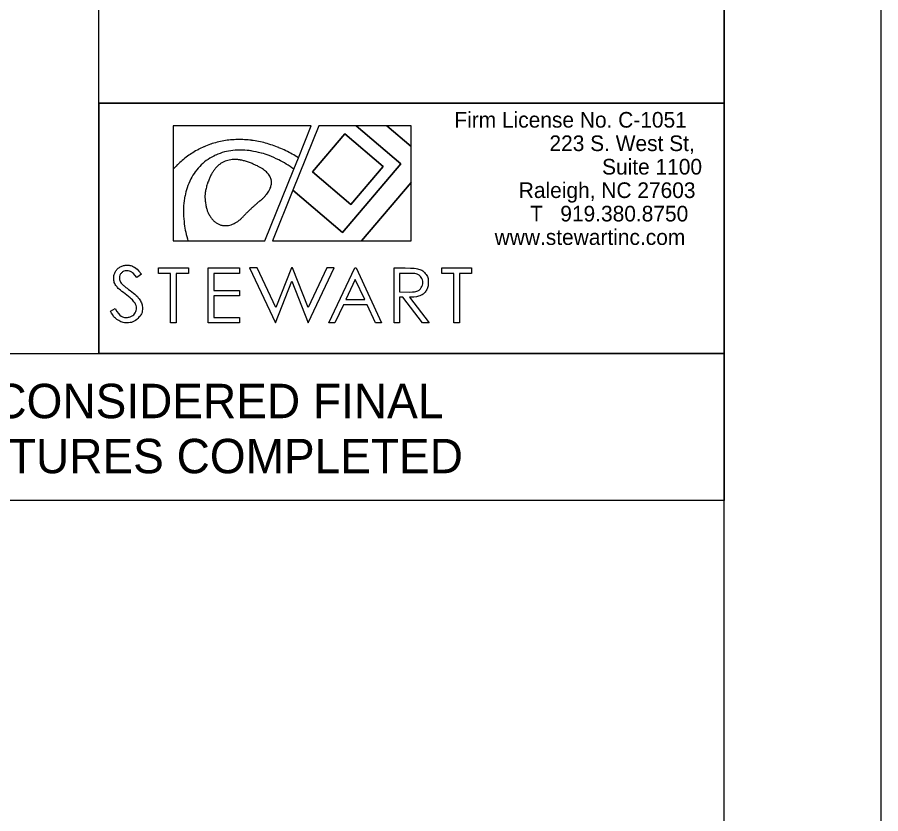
# Model space of a CAD drawing. Extents: x 885343.6 to 885383.5, y 651350.8 to 651372.8.
# Drawn here: x 885374.838 to 885377.598, y 651367.24 to 651369.786 of the extents above; entities that cross this region are included whole.
import ezdxf

# ---------------------------------------------------------------- set-up
doc = ezdxf.new("R2010")
doc.units = 0
for name, color, linetype in [('Default', 7, 'Continuous'), ('Sheet Plan And Profile CELL', 7, 'Continuous'), ('Sheet Plan CELL', 7, 'Continuous'), ('Sheet Sticker Exception Certification CELL', 7, 'Continuous'), ('Stewart Plot Border Xerox6279 and LJ5000', 7, 'Continuous')]:
    doc.layers.add(name, color=color, linetype=linetype)

msp = doc.modelspace()

# ---------------------------------------------------------------- linework, layer by layer
at = {"layer": 'Default'}
for p, q in [((885375.7773, 651369.4388), (885375.3358, 651369.4388)), ((885375.3358, 651369.4388), (885375.3358, 651369.2998)), ((885375.8019, 651369.4388), (885375.7189, 651369.2326)), ((885375.7362, 651369.3367), (885375.7773, 651369.4388)), ((885375.9209, 651369.4388), (885375.8019, 651369.4388)), ((885375.9209, 651369.4388), (885376.0639, 651369.317)), ((885376.0188, 651369.4388), (885375.9209, 651369.4388)), ((885376.0639, 651369.317), (885375.9209, 651369.4388)), ((885376.0965, 651369.4388), (885376.0188, 651369.4388)), ((885376.0188, 651369.4388), (885376.0965, 651369.3727)), ((885376.0965, 651369.3727), (885376.0188, 651369.4388)), ((885376.0965, 651369.3727), (885376.0965, 651369.4388)), ((885375.5862, 651369.3923), (885375.5864, 651369.3923)), ((885375.4347, 651369.372), (885375.4342, 651369.3714)), ((885375.456, 651369.3801), (885375.4551, 651369.3798)), ((885376.0965, 651369.2574), (885376.0965, 651369.3727)), ((885375.5845, 651369.3582), (885375.5853, 651369.3586)), ((885375.6959, 651369.3591), (885375.696, 651369.359)), ((885375.7216, 651369.3005), (885375.7362, 651369.3367)), ((885376.0639, 651369.317), (885375.8772, 651369.0978)), ((885375.8772, 651369.0978), (885376.0639, 651369.317)), ((885375.9036, 651369.187), (885376.0073, 651369.3087)), ((885375.3358, 651369.2998), (885375.3358, 651369.0708)), ((885375.6293, 651369.0708), (885375.7216, 651369.3005)), ((885376.0965, 651369.2574), (885375.9376, 651369.0708)), ((885375.9376, 651369.0708), (885376.0965, 651369.2574)), ((885376.0965, 651369.0708), (885376.0965, 651369.2574)), ((885375.7189, 651369.2326), (885375.6539, 651369.0708)), ((885375.8772, 651369.0978), (885375.7189, 651369.2326)), ((885375.7189, 651369.2326), (885375.8772, 651369.0978)), ((885375.3358, 651369.0708), (885375.3833, 651369.0708)), ((885375.3833, 651369.0708), (885375.6293, 651369.0708)), ((885375.6539, 651369.0708), (885375.9376, 651369.0708)), ((885375.9376, 651369.0708), (885376.0965, 651369.0708)), ((885375.6041, 651368.9842), (885375.5802, 651368.9842)), ((885375.5802, 651368.9842), (885375.6626, 651368.8092)), ((885375.6636, 651368.8581), (885375.6041, 651368.9842)), ((885375.7141, 651368.9842), (885375.6636, 651368.8581)), ((885375.7175, 651368.9842), (885375.7141, 651368.9842)), ((885375.767, 651368.8581), (885375.7175, 651368.9842)), ((885375.8266, 651368.9842), (885375.767, 651368.8581)), ((885375.7678, 651368.8092), (885375.8504, 651368.9842)), ((885375.8504, 651368.9842), (885375.8266, 651368.9842)), ((885375.6626, 651368.8092), (885375.7157, 651368.9417)), ((885375.7157, 651368.9417), (885375.7678, 651368.8092))]:
    msp.add_line(p, q, dxfattribs=at)
msp.add_lwpolyline([(885377.0978, 651369.5109), (885375.0978, 651369.5109), (885375.0978, 651368.7109), (885377.0978, 651368.7109)], close=True, dxfattribs=at)
for points in [[(885375.7814, 651369.2911), (885375.885, 651369.4128), (885376.0073, 651369.3087), (885375.9036, 651369.187), (885375.7814, 651369.2911)], [(885376.0073, 651369.3087), (885375.885, 651369.4128), (885375.7814, 651369.2911), (885375.9036, 651369.187)], [(885375.4155, 651369.3626), (885375.417, 651369.3635)], [(885375.6179, 651369.3515), (885375.617, 651369.3511)], [(885375.3499, 651369.3143), (885375.3487, 651369.3135)], [(885375.6129, 651369.1982), (885375.6112, 651369.1969)], [(885375.6155, 651369.1998), (885375.6141, 651369.199)], [(885375.6092, 651369.1953), (885375.6068, 651369.1933)], [(885375.5652, 651369.1544), (885375.5632, 651369.1524)], [(885375.2889, 651368.9671), (885375.2889, 651368.9842), (885375.3847, 651368.9842), (885375.3847, 651368.9671), (885375.3457, 651368.9671), (885375.3457, 651368.8092), (885375.3279, 651368.8092), (885375.3279, 651368.9671), (885375.2889, 651368.9671)], [(885375.448, 651368.9842), (885375.5484, 651368.9842), (885375.5484, 651368.9671), (885375.4655, 651368.9671), (885375.4655, 651368.9122), (885375.5477, 651368.9122), (885375.5477, 651368.8951), (885375.4655, 651368.8951), (885375.4655, 651368.8263), (885375.5477, 651368.8263), (885375.5477, 651368.8092), (885375.448, 651368.8092), (885375.448, 651368.9842)], [(885375.9205, 651368.9842), (885376.0021, 651368.8092), (885375.9832, 651368.8092), (885375.9557, 651368.8669), (885375.8803, 651368.8669), (885375.8531, 651368.8092), (885375.8336, 651368.8092), (885375.9162, 651368.9842), (885375.9205, 651368.9842)], [(885376.0424, 651368.9842), (885376.0772, 651368.9842)], [(885376.0913, 651368.8904), (885376.1542, 651368.8092), (885376.1325, 651368.8092), (885376.0696, 651368.8904), (885376.0598, 651368.8904), (885376.0598, 651368.8092), (885376.0424, 651368.8092), (885376.0424, 651368.9842)], [(885376.1943, 651368.9671), (885376.1943, 651368.9842), (885376.2901, 651368.9842), (885376.2901, 651368.9671), (885376.2511, 651368.9671), (885376.2511, 651368.8092), (885376.2333, 651368.8092), (885376.2333, 651368.9671), (885376.1943, 651368.9671)], [(885375.2344, 651368.9643), (885375.2202, 651368.9535)], [(885376.0598, 651368.9671), (885376.0598, 651368.9075), (885376.0899, 651368.9073)], [(885376.0906, 651368.9671), (885376.0598, 651368.9671)], [(885375.9182, 651368.9471), (885375.8883, 651368.8837), (885375.9481, 651368.8837), (885375.9182, 651368.9471)], [(885375.1351, 651368.8462), (885375.15, 651368.8551)]]:
    msp.add_lwpolyline(points, dxfattribs=at)
for centre, radius, start, end in [((885375.5456, 651369.1125), 0.2822, 99.7438, 104.178), ((885375.5456, 651369.1125), 0.2822, 99.7438, 104.178), ((885375.5462, 651369.1088), 0.286, 95.339, 99.7438), ((885375.5462, 651369.1088), 0.286, 95.339, 99.7438), ((885375.5467, 651369.1035), 0.2913, 91.0141, 95.339), ((885375.5467, 651369.1035), 0.2913, 91.0141, 95.339), ((885375.547, 651369.0858), 0.309, 86.8145, 91.0141), ((885375.547, 651369.0858), 0.309, 86.8145, 91.0141), ((885375.547, 651369.0858), 0.309, 82.6822, 86.8145), ((885375.547, 651369.0858), 0.309, 82.6822, 86.8145), ((885375.5431, 651369.0564), 0.3386, 78.75, 82.6822), ((885375.5431, 651369.0564), 0.3386, 78.75, 82.6822), ((885375.5495, 651369.1106), 0.2855, 117.649, 121.981), ((885375.5495, 651369.1106), 0.2855, 117.649, 121.981), ((885375.5372, 651369.1304), 0.2622, 113.1331, 117.649), ((885375.5372, 651369.1304), 0.2622, 113.1331, 117.649), ((885375.5456, 651369.1125), 0.2822, 108.6948, 113.1331), ((885375.5456, 651369.1125), 0.2822, 108.6948, 113.1331), ((885375.5427, 651369.1238), 0.2705, 104.178, 108.6948), ((885375.5427, 651369.1238), 0.2705, 104.178, 108.6948), ((885375.5454, 651369.0679), 0.3269, 74.8634, 78.75), ((885375.5454, 651369.0679), 0.3269, 74.8634, 78.75), ((885375.5332, 651369.0228), 0.3736, 71.2279, 74.8634), ((885375.5332, 651369.0228), 0.3736, 71.2279, 74.8634), ((885375.5406, 651369.0448), 0.3505, 67.6108, 71.2279), ((885375.5406, 651369.0448), 0.3505, 67.6108, 71.2279), ((885375.5172, 651368.9879), 0.4119, 64.2747, 67.6108), ((885375.5172, 651368.9879), 0.4119, 64.2747, 67.6108), ((885375.5584, 651369.1016), 0.2979, 126.3831, 130.5125), ((885375.5584, 651369.1016), 0.2979, 126.3831, 130.5125), ((885375.5372, 651369.1304), 0.2622, 121.981, 126.3831), ((885375.5372, 651369.1304), 0.2622, 121.981, 126.3831), ((885375.538, 651369.198), 0.1613, 114.2575, 124.1721), ((885375.538, 651369.198), 0.1613, 114.2575, 124.1721), ((885375.5476, 651369.1768), 0.1845, 104.9898, 114.2575), ((885375.5476, 651369.1768), 0.1845, 104.9898, 114.2575), ((885375.5446, 651369.1878), 0.1731, 95.9703, 104.9898), ((885375.5446, 651369.1878), 0.1731, 95.9703, 104.9898), ((885375.5515, 651369.1221), 0.2391, 88.2991, 95.9703), ((885375.5515, 651369.1221), 0.2391, 88.2991, 95.9703), ((885375.5525, 651369.1571), 0.2041, 80.7637, 88.2991), ((885375.5525, 651369.1571), 0.2041, 80.7637, 88.2991), ((885375.5338, 651369.0465), 0.3158, 74.7103, 80.7637), ((885375.5338, 651369.0465), 0.3158, 74.7103, 80.7637), ((885375.5536, 651369.1163), 0.2439, 68.5824, 74.7103), ((885375.5536, 651369.1163), 0.2439, 68.5824, 74.7103), ((885375.4966, 651368.9711), 0.3999, 63.7978, 68.5824), ((885375.4966, 651368.9711), 0.3999, 63.7978, 68.5824), ((885375.5243, 651369.0029), 0.3953, 60.9284, 64.2747), ((885375.5243, 651369.0029), 0.3953, 60.9284, 64.2747), ((885375.5243, 651369.0029), 0.3953, 57.5922, 60.9284), ((885375.5243, 651369.0029), 0.3953, 57.5922, 60.9284), ((885375.5495, 651369.1106), 0.2855, 134.7069, 138.485), ((885375.5495, 651369.1106), 0.2855, 134.7069, 138.485), ((885375.5452, 651369.117), 0.2776, 130.5125, 134.7069), ((885375.5452, 651369.117), 0.2776, 130.5125, 134.7069), ((885375.5488, 651369.1873), 0.1764, 134.1821, 143.7045), ((885375.5488, 651369.1873), 0.1764, 134.1821, 143.7045), ((885375.5371, 651369.1993), 0.1597, 124.1721, 134.1821), ((885375.5371, 651369.1993), 0.1597, 124.1721, 134.1821), ((885375.5378, 651369.2463), 0.0874, 132.8496, 139.1543), ((885375.5378, 651369.2463), 0.0874, 132.8496, 139.1543), ((885375.534, 651369.2503), 0.0819, 126.1002, 132.8496), ((885375.534, 651369.2503), 0.0819, 126.1002, 132.8496), ((885375.5297, 651369.2562), 0.0746, 119.026, 126.1002), ((885375.5297, 651369.2562), 0.0746, 119.026, 126.1002), ((885375.5291, 651369.2574), 0.0733, 111.8278, 119.026), ((885375.5291, 651369.2574), 0.0733, 111.8278, 119.026), ((885375.5298, 651369.2555), 0.0753, 104.7285, 111.8278), ((885375.5298, 651369.2555), 0.0753, 104.7285, 111.8278), ((885375.5305, 651369.2529), 0.078, 97.9017, 104.7285), ((885375.5305, 651369.2529), 0.078, 97.9017, 104.7285), ((885375.5322, 651369.2412), 0.0898, 91.5398, 97.9017), ((885375.5322, 651369.2412), 0.0898, 91.5398, 97.9017), ((885375.5323, 651369.2343), 0.0968, 85.6825, 91.5398), ((885375.5323, 651369.2343), 0.0968, 85.6825, 91.5398), ((885375.5306, 651369.2109), 0.1202, 80.427, 85.6825), ((885375.5306, 651369.2109), 0.1202, 80.427, 85.6825), ((885375.5286, 651369.1995), 0.1317, 75.6971, 80.427), ((885375.5286, 651369.1995), 0.1317, 75.6971, 80.427), ((885375.5193, 651369.1628), 0.1697, 71.5292, 75.6971), ((885375.5193, 651369.1628), 0.1697, 71.5292, 75.6971), ((885375.5064, 651369.1242), 0.2103, 67.7999, 71.5292), ((885375.5064, 651369.1242), 0.2103, 67.7999, 71.5292), ((885375.5222, 651369.163), 0.1684, 63.632, 67.7999), ((885375.5222, 651369.163), 0.1684, 63.632, 67.7999), ((885375.5471, 651369.1917), 0.132, 63.9022, 67.7899), ((885375.5471, 651369.1917), 0.132, 63.9022, 67.7899), ((885375.529, 651369.1546), 0.1733, 60.5091, 63.9022), ((885375.529, 651369.1546), 0.1733, 60.5091, 63.9022), ((885375.5338, 651369.0465), 0.3158, 58.7784, 63.7978), ((885375.5338, 651369.0465), 0.3158, 58.7784, 63.7978), ((885375.5173, 651369.0194), 0.3475, 53.9938, 58.7784), ((885375.5173, 651369.0194), 0.3475, 53.9938, 58.7784), ((885375.5381, 651369.1951), 0.1631, 143.7045, 153.1024), ((885375.5381, 651369.1951), 0.1631, 143.7045, 153.1024), ((885375.5866, 651369.2132), 0.1466, 150.0914, 154.7022), ((885375.5866, 651369.2132), 0.1466, 150.0914, 154.7022), ((885375.5596, 651369.2288), 0.1154, 144.895, 150.0914), ((885375.5596, 651369.2288), 0.1154, 144.895, 150.0914), ((885375.5514, 651369.2345), 0.1054, 139.1543, 144.895), ((885375.5514, 651369.2345), 0.1054, 139.1543, 144.895), ((885375.5487, 651369.1894), 0.1333, 56.6214, 60.5091), ((885375.5487, 651369.1894), 0.1333, 56.6214, 60.5091), ((885375.5683, 651369.2193), 0.0975, 52.0757, 56.6214), ((885375.5683, 651369.2193), 0.0975, 52.0757, 56.6214), ((885375.5755, 651369.2285), 0.0858, 46.8444, 52.0757), ((885375.5755, 651369.2285), 0.0858, 46.8444, 52.0757), ((885375.5906, 651369.2446), 0.0638, 40.7768, 46.8444), ((885375.5906, 651369.2446), 0.0638, 40.7768, 46.8444), ((885375.596, 651369.2492), 0.0567, 33.8961, 40.7768), ((885375.596, 651369.2492), 0.0567, 33.8961, 40.7768), ((885375.6055, 651369.2556), 0.0452, 26.1882, 33.8961), ((885375.6055, 651369.2556), 0.0452, 26.1882, 33.8961), ((885375.59, 651369.1688), 0.2213, 153.1024, 161.1689), ((885375.59, 651369.1688), 0.2213, 153.1024, 161.1689), ((885375.6921, 651369.1746), 0.2591, 162.4501, 165.6937), ((885375.6921, 651369.1746), 0.2591, 162.4501, 165.6937), ((885375.6447, 651369.1896), 0.2093, 158.8258, 162.4501), ((885375.6447, 651369.1896), 0.2093, 158.8258, 162.4501), ((885375.6003, 651369.2068), 0.1617, 154.7022, 158.8258), ((885375.6003, 651369.2068), 0.1617, 154.7022, 158.8258), ((885375.6084, 651369.2571), 0.042, 17.8594, 26.1882), ((885375.6084, 651369.2571), 0.042, 17.8594, 26.1882), ((885375.6117, 651369.2581), 0.0386, 9.1711, 17.8594), ((885375.6117, 651369.2581), 0.0386, 9.1711, 17.8594), ((885375.6042, 651369.2585), 0.046, 344.6304, 352.2444), ((885375.6042, 651369.2585), 0.046, 344.6304, 352.2444), ((885375.6115, 651369.2581), 0.0387, 0.507, 9.1711), ((885375.6115, 651369.2581), 0.0387, 0.507, 9.1711), ((885375.6077, 651369.2581), 0.0425, 352.2444, 0.507), ((885375.6077, 651369.2581), 0.0425, 352.2444, 0.507), ((885375.5585, 651369.1795), 0.1881, 161.1689, 169.1279), ((885375.5585, 651369.1795), 0.1881, 161.1689, 169.1279), ((885375.5894, 651369.2124), 0.1518, 174.9583, 179.1125), ((885375.5894, 651369.2124), 0.1518, 174.9583, 179.1125), ((885375.6421, 651369.1873), 0.2075, 165.6937, 169.3181), ((885375.6421, 651369.1873), 0.2075, 165.6937, 169.3181), ((885375.5556, 651369.2818), 0.1002, 322.2915, 326.7539), ((885375.5556, 651369.2818), 0.1002, 322.2915, 326.7539), ((885375.5657, 651369.2752), 0.0882, 326.7539, 331.8907), ((885375.5657, 651369.2752), 0.0882, 326.7539, 331.8907), ((885375.5858, 651369.2645), 0.0655, 331.8907, 337.8545), ((885375.5858, 651369.2645), 0.0655, 331.8907, 337.8545), ((885375.5926, 651369.2617), 0.0581, 337.8545, 344.6304), ((885375.5926, 651369.2617), 0.0581, 337.8545, 344.6304), ((885375.6595, 651369.1601), 0.291, 169.1279, 175.5255), ((885375.6595, 651369.1601), 0.291, 169.1279, 175.5255), ((885375.5732, 651369.2127), 0.1356, 179.1125, 183.5072), ((885375.5732, 651369.2127), 0.1356, 179.1125, 183.5072), ((885375.6126, 651369.2151), 0.175, 183.5072, 187.6613), ((885375.6126, 651369.2151), 0.175, 183.5072, 187.6613), ((885375.6929, 651369.0929), 0.1322, 128.1219, 129.2494), ((885375.6929, 651369.0929), 0.1322, 128.1219, 129.2494), ((885375.6501, 651369.1475), 0.0629, 126.2742, 128.1219), ((885375.6323, 651369.1717), 0.0329, 123.718, 126.2741), ((885375.6323, 651369.1717), 0.0329, 123.718, 126.2741), ((885375.6168, 651369.1949), 0.00499, 118.0607, 123.718), ((885375.626, 651369.1777), 0.0244, 115.5046, 118.0608), ((885375.5259, 651369.3016), 0.1356, 311.3243, 315.1414), ((885375.5259, 651369.3016), 0.1356, 311.3243, 315.1414), ((885375.4959, 651369.3314), 0.1779, 315.1414, 318.4744), ((885375.4959, 651369.3314), 0.1779, 315.1414, 318.4744), ((885375.5266, 651369.3043), 0.137, 318.4744, 322.2915), ((885375.5266, 651369.3043), 0.137, 318.4744, 322.2915), ((885375.5937, 651369.1653), 0.225, 175.5255, 181.9873), ((885375.5937, 651369.1653), 0.225, 175.5255, 181.9873), ((885375.5459, 651369.2061), 0.1078, 187.6614, 192.9555), ((885375.5459, 651369.2061), 0.1078, 187.6614, 192.9555), ((885375.5772, 651369.2133), 0.1398, 192.9555, 198.184), ((885375.5772, 651369.2133), 0.1398, 192.9555, 198.184), ((885375.5289, 651369.1975), 0.0891, 198.184, 204.7361), ((885375.5289, 651369.1975), 0.0891, 198.184, 204.7361), ((885376.2273, 651368.4918), 0.9368, 133.5368, 133.8764), ((885376.2273, 651368.4918), 0.9368, 133.5368, 133.8764), ((885376.1241, 651368.6004), 0.787, 133.1663, 133.5368), ((885376.1241, 651368.6004), 0.787, 133.1663, 133.5368), ((885376.1794, 651368.5414), 0.8679, 132.7975, 133.1663), ((885376.1794, 651368.5414), 0.8679, 132.7975, 133.1663), ((885376.0829, 651368.6456), 0.7257, 132.3943, 132.7975), ((885376.0829, 651368.6456), 0.7257, 132.3943, 132.7975), ((885376.0392, 651368.6935), 0.6609, 131.9515, 132.3943), ((885376.0392, 651368.6935), 0.6609, 131.9515, 132.3943), ((885375.9606, 651368.781), 0.5433, 131.4632, 131.9515), ((885375.9606, 651368.781), 0.5433, 131.4632, 131.9515), ((885375.8684, 651368.8853), 0.4042, 130.8651, 131.4632), ((885375.8684, 651368.8853), 0.4042, 130.8651, 131.4632), ((885375.8108, 651368.9518), 0.3161, 130.1887, 130.8651), ((885375.8108, 651368.9518), 0.3161, 130.1887, 130.8651), ((885375.7297, 651369.0478), 0.1905, 129.2494, 130.1887), ((885375.7406, 651369.1704), 0.3719, 181.9873, 187.0116), ((885375.7406, 651369.1704), 0.3719, 181.9873, 187.0116), ((885375.5414, 651369.2032), 0.1028, 204.7361, 211.5103), ((885375.5414, 651369.2032), 0.1028, 204.7361, 211.5103), ((885375.5139, 651369.1864), 0.0706, 211.5103, 219.6861), ((885375.5139, 651369.1864), 0.0706, 211.5103, 219.6861), ((885375.489, 651369.2101), 0.0937, 308.3257, 314.0568), ((885375.489, 651369.2101), 0.0937, 308.3257, 314.0568), ((885375.4861, 651369.2132), 0.0979, 314.0568, 319.6622), ((885375.4861, 651369.2132), 0.0979, 314.0568, 319.6622), ((885375.9618, 651368.7653), 0.5556, 135.8419, 136.2162), ((885375.9618, 651368.7653), 0.5556, 135.8419, 136.2162), ((885375.8138, 651368.9091), 0.3493, 135.3698, 135.8419), ((885376.0296, 651368.696), 0.6526, 134.9955, 135.3698), ((885376.0296, 651368.696), 0.6526, 134.9955, 135.3698), ((885375.9632, 651368.7625), 0.5586, 134.5909, 134.9955), ((885375.9632, 651368.7625), 0.5586, 134.5909, 134.9955), ((885376.1657, 651368.5571), 0.847, 134.2487, 134.5909), ((885376.1657, 651368.5571), 0.847, 134.2487, 134.5909), ((885376.0736, 651368.6516), 0.7151, 133.8764, 134.2487), ((885376.0736, 651368.6516), 0.7151, 133.8764, 134.2487), ((885375.6664, 651369.1613), 0.2971, 187.0116, 192.2545), ((885375.6664, 651369.1613), 0.2971, 187.0116, 192.2545), ((885375.5154, 651369.1876), 0.0724, 219.6861, 228.4088), ((885375.5154, 651369.1876), 0.0724, 219.6861, 228.4088), ((885375.5056, 651369.1765), 0.0577, 228.4088, 238.184), ((885375.5056, 651369.1765), 0.0577, 228.4088, 238.184), ((885375.5037, 651369.1736), 0.0542, 238.184, 248.5685), ((885375.5037, 651369.1736), 0.0542, 238.184, 248.5685), ((885375.5039, 651369.1739), 0.0546, 248.5685, 258.9188), ((885375.5039, 651369.1739), 0.0546, 248.5685, 258.9188), ((885375.5027, 651369.1681), 0.0486, 258.9188, 269.5093), ((885375.5027, 651369.1681), 0.0486, 258.9188, 269.5093), ((885375.5029, 651369.1827), 0.0632, 269.5093, 278.793), ((885375.5029, 651369.1827), 0.0632, 269.5093, 278.793), ((885375.5044, 651369.173), 0.0534, 278.793, 288.0103), ((885375.5044, 651369.173), 0.0534, 278.793, 288.0103), ((885375.495, 651369.2016), 0.0835, 288.0103, 295.379), ((885375.495, 651369.2016), 0.0835, 288.0103, 295.379), ((885375.5028, 651369.1853), 0.0655, 295.379, 302.7203), ((885375.5028, 651369.1853), 0.0655, 295.379, 302.7203), ((885375.4775, 651369.2247), 0.1123, 302.7203, 308.3257), ((885375.4775, 651369.2247), 0.1123, 302.7203, 308.3257), ((885375.6922, 651369.1669), 0.3235, 192.2545, 197.2789), ((885375.6922, 651369.1669), 0.3235, 192.2545, 197.2789)]:
    msp.add_arc(centre, radius, start, end, dxfattribs=at)
for points in [[(885375.15, 651368.8551), (885375.1657, 651368.8262), (885375.1862, 651368.8262), (885375.195, 651368.8262), (885375.2028, 651368.8303), (885375.2105, 651368.8344), (885375.2145, 651368.8413), (885375.2186, 651368.8482), (885375.2186, 651368.8559), (885375.2186, 651368.8647), (885375.2126, 651368.8732), (885375.2044, 651368.8848), (885375.1827, 651368.9012), (885375.1608, 651368.9178), (885375.1554, 651368.9251), (885375.1462, 651368.9375), (885375.1462, 651368.9519), (885375.1462, 651368.9634), (885375.1516, 651368.9728), (885375.1571, 651368.9822), (885375.167, 651368.9876), (885375.1769, 651368.993), (885375.1886, 651368.993), (885375.2009, 651368.993), (885375.2117, 651368.9869), (885375.2224, 651368.9807), (885375.2344, 651368.9643)], [(885376.0772, 651368.9842), (885376.1062, 651368.9842), (885376.1166, 651368.9818), (885376.1321, 651368.9782), (885376.1419, 651368.9665), (885376.1516, 651368.9548), (885376.1516, 651368.9376), (885376.1516, 651368.9233), (885376.1449, 651368.9124), (885376.1382, 651368.9016), (885376.1257, 651368.8961), (885376.1133, 651368.8905), (885376.0913, 651368.8904)], [(885375.2202, 651368.9535), (885375.2103, 651368.9665), (885375.2033, 651368.9707), (885375.1964, 651368.9748), (885375.1882, 651368.9748), (885375.1776, 651368.9748), (885375.1709, 651368.9684), (885375.1641, 651368.962), (885375.1641, 651368.9526), (885375.1641, 651368.9469), (885375.1665, 651368.9416), (885375.1689, 651368.9362), (885375.1752, 651368.9299), (885375.1787, 651368.9266), (885375.1978, 651368.9124), (885375.2205, 651368.8957), (885375.229, 651368.8826), (885375.2374, 651368.8695), (885375.2374, 651368.8563), (885375.2374, 651368.8373), (885375.223, 651368.8232), (885375.2085, 651368.8092), (885375.1879, 651368.8092), (885375.1719, 651368.8092), (885375.159, 651368.8177), (885375.146, 651368.8262), (885375.1351, 651368.8462)], [(885376.0899, 651368.9073), (885376.1074, 651368.9073), (885376.1158, 651368.9106), (885376.1242, 651368.914), (885376.1289, 651368.9213), (885376.1336, 651368.9286), (885376.1336, 651368.9377), (885376.1336, 651368.9465), (885376.1289, 651368.9537), (885376.1241, 651368.9609), (885376.1164, 651368.964), (885376.1086, 651368.9671), (885376.0906, 651368.9671)]]:
    msp.add_open_spline(points, degree=3, dxfattribs=at)
at = {"layer": 'Sheet Plan And Profile CELL'}
for points in [[(885375.0978, 651371.7609), (885377.0978, 651371.7609), (885377.0978, 651369.5109), (885375.0978, 651369.5109)], [(885375.0978, 651369.5109), (885377.0978, 651369.5109), (885377.0978, 651368.7109), (885375.0978, 651368.7109)]]:
    msp.add_lwpolyline(points, close=True, dxfattribs=at)
at = {"layer": 'Sheet Plan CELL'}
msp.add_lwpolyline([(885377.0978, 651372.2619), (885347.0978, 651372.2619), (885347.0978, 651351.2619), (885377.0978, 651351.2619)], close=True, dxfattribs=at)
at = {"layer": 'Sheet Sticker Exception Certification CELL'}
for p, q in [((885373.0978, 651368.7109), (885377.0978, 651368.7109)), ((885377.0978, 651368.7106), (885377.0978, 651368.2406)), ((885377.0978, 651368.2409), (885373.0978, 651368.2409))]:
    msp.add_line(p, q, dxfattribs=at)
at = {"layer": 'Stewart Plot Border Xerox6279 and LJ5000'}
msp.add_lwpolyline([(885343.5978, 651372.7619), (885377.5978, 651372.7619), (885377.5978, 651350.7619), (885343.5978, 651350.7619)], close=True, dxfattribs=at)

# ---------------------------------------------------------------- texts
at = {"layer": 'Default'}
for s, p in [('Firm License No. C-1051', (885376.2347, 651369.4329)), ('223 S. West St,', (885376.5388, 651369.3579)), ('Suite 1100', (885376.7069, 651369.2829)), ('Raleigh, NC 27603', (885376.4407, 651369.2079)), ('T   919.380.8750', (885376.4769, 651369.1329)), ('www.stewartinc.com', (885376.3637, 651369.0579))]:
    msp.add_text(s, height=0.05, rotation=0, dxfattribs=at).set_placement(p)
at = {"layer": 'Sheet Sticker Exception Certification CELL'}
for s, p in [('DOCUMENT NOT CONSIDERED FINAL', (885373.5191, 651368.504)), ('UNLESS ALL SIGNATURES COMPLETED', (885373.4177, 651368.328))]:
    msp.add_text(s, height=0.11, rotation=0, dxfattribs=at).set_placement(p)

doc.saveas('drawing.dxf')
